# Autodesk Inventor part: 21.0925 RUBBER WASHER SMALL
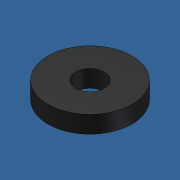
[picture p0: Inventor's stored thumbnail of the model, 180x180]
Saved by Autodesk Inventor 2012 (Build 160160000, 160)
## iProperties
Created: 2013-10
Part Number: 21.0925 RUBBER WASHER SMALL
Material: Rubber
Document SubType Name: Modeling
Designer: Admin
Mass: 2.05907 g
Surface Area: 14.05 cm^2
Volume: 2.21406 cm^3
Density: 0.93 g/cm^3
Author: Admin
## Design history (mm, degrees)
sketch "Sketch1"
  geometry: C1 r 4.25 at (0, 0); C2 r 12.5 at (0, 0); 1 further point
  constraints: 2 centre point, 2 coincident
  dimensions: "d0" = 8.5 diameter of C1; "d1" = 25 diameter of C2
extrude "Extrusion1" new body sketch "Sketch1" distance "d2" = 5.1; taper "d3" = 0 deg
body "Solid1"
